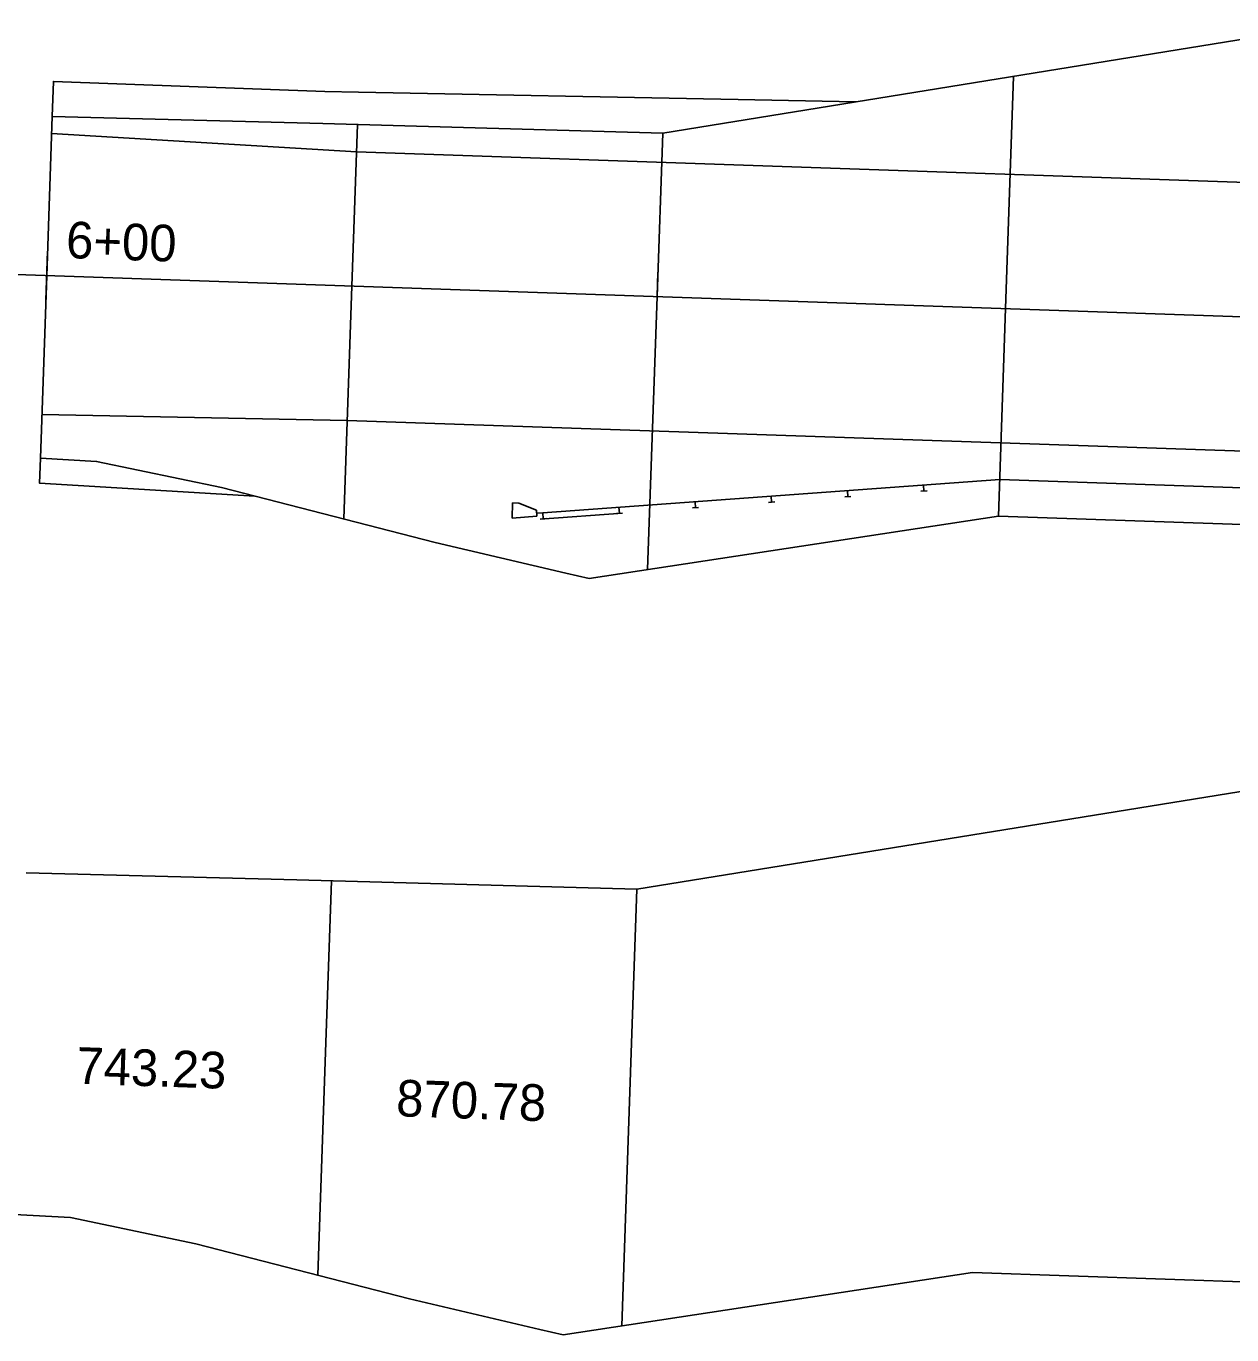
# Model space of a CAD drawing. Extents: x 2191309 to 2193046, y 863659 to 865133.
# Drawn here: x 2191516.5 to 2191615.2, y 865006.3 to 865113.4 of the extents above; entities that cross this region are included whole.
import ezdxf

# ---------------------------------------------------------------- set-up
doc = ezdxf.new("R2010")
doc.units = 0
for name, color, linetype in [('D_Guardrail_Beam_Rt', 7, 'Continuous'), ('D_Guardrail_End_MidSplice', 7, 'Continuous'), ('D_Roadway_Centerline', 7, 'Continuous'), ('D_Roadway_Centerline_Text', 7, 'Continuous'), ('D_Roadway_Drive_Gravel', 7, 'Continuous'), ('D_Roadway_Edge_Shoulder', 7, 'Continuous'), ('D_Roadway_Edge_TW', 7, 'Continuous'), ('FRAME', 7, 'Continuous'), ('JUNK', 7, 'Continuous')]:
    doc.layers.add(name, color=color, linetype=linetype)

msp = doc.modelspace()

# ---------------------------------------------------------------- linework, layer by layer
at = {"layer": 'D_Guardrail_Beam_Rt'}
msp.add_line((2191596.21, 865076.32), (2191668.04, 865073.86), dxfattribs=at)
at = {"layer": 'D_Guardrail_End_MidSplice'}
for p, q in [((2191596.21, 865076.32), (2191558.81, 865073.61)), ((2191589.97, 865075.87), (2191590.01, 865075.37)), ((2191571.27, 865074.51), (2191571.31, 865074.01)), ((2191577.51, 865074.97), (2191577.54, 865074.47)), ((2191584.03, 865074.94), (2191583.53, 865074.9)), ((2191583.74, 865075.42), (2191583.78, 865074.92)), ((2191590.26, 865075.39), (2191589.76, 865075.36)), ((2191556.29, 865073.17), (2191556.33, 865074.42)), ((2191556.33, 865074.42), (2191556.83, 865074.4)), ((2191556.83, 865074.4), (2191558.29, 865073.82)), ((2191558.29, 865073.82), (2191558.33, 865073.32)), ((2191558.81, 865073.61), (2191558.31, 865073.57)), ((2191565.32, 865073.58), (2191558.59, 865073.09)), ((2191558.81, 865073.61), (2191558.84, 865073.11)), ((2191565.32, 865073.58), (2191564.83, 865073.54)), ((2191565.04, 865074.06), (2191565.08, 865073.56)), ((2191571.56, 865074.03), (2191571.06, 865074)), ((2191577.79, 865074.49), (2191577.29, 865074.45)), ((2191558.33, 865073.32), (2191556.29, 865073.17)), ((2191559.09, 865073.13), (2191558.59, 865073.09))]:
    msp.add_line(p, q, dxfattribs=at)
at = {"layer": 'D_Roadway_Centerline'}
msp.add_line((2191489.64, 865093.99), (2191792.64, 865083.59), dxfattribs=at)
at = {"layer": 'D_Roadway_Centerline_Text'}
for points in [[(2191518.26, 865095.01), (2191518.12, 865091.01)], [(2191568.23, 865093.29), (2191568.16, 865091.3)]]:
    msp.add_lwpolyline(points, dxfattribs=at)
at = {"layer": 'D_Roadway_Drive_Gravel'}
for points in [[(2191518.64, 865106.05), (2191518.64, 865106.05), (2191518.74, 865108.92), (2191540.96, 865108.08), (2191543.72, 865108.03), (2191574.81, 865107.43), (2191584.44, 865107.24)], [(2191517.68, 865078.07), (2191517.61, 865076.02), (2191535.24, 865074.96)]]:
    msp.add_lwpolyline(points, dxfattribs=at)
at = {"layer": 'D_Roadway_Edge_Shoulder'}
for p, q in [((2191622.71, 865113.44), (2191568.62, 865104.69)), ((2191518.19, 865093.01), (2191518.64, 865106.05)), ((2191517.68, 865078.07), (2191518.19, 865093.01)), ((2191562.6, 865068.22), (2191596.1, 865073.33)), ((2191596.1, 865073.33), (2191697, 865069.86)), ((2191620.58, 865051.53), (2191566.49, 865042.78)), ((2191560.48, 865006.31), (2191593.98, 865011.42)), ((2191593.98, 865011.42), (2191694.88, 865007.95))]:
    msp.add_line(p, q, dxfattribs=at)
for points in [[(2191568.62, 865104.69), (2191540.8, 865105.46), (2191518.64, 865106.05)], [(2191517.68, 865078.07), (2191522.27, 865077.81), (2191532.51, 865075.66), (2191550, 865071.18), (2191560.68, 865068.67), (2191562.6, 865068.22)], [(2191566.49, 865042.78), (2191538.67, 865043.55), (2191516.51, 865044.14)], [(2191515.55, 865016.16), (2191520.14, 865015.91), (2191530.39, 865013.75), (2191547.88, 865009.27), (2191558.56, 865006.76), (2191560.48, 865006.31)]]:
    msp.add_lwpolyline(points, dxfattribs=at)
at = {"layer": 'D_Roadway_Edge_TW'}
for points in [[(2191518.59, 865104.66), (2191543.55, 865103.15), (2191648.1, 865099.56), (2191698.08, 865101.18)], [(2191517.8, 865081.65), (2191542.8, 865081.16), (2191647.35, 865077.57), (2191697.09, 865072.53)]]:
    msp.add_lwpolyline(points, dxfattribs=at)
at = {"layer": 'JUNK'}
for p, q in [((2191596.69, 865090.32), (2191597.34, 865109.33)), ((2191543.17, 865092.15), (2191543.63, 865105.38)), ((2191568.16, 865091.3), (2191568.62, 865104.69)), ((2191542.52, 865073.1), (2191543.17, 865092.15)), ((2191567.39, 865068.95), (2191568.16, 865091.3)), ((2191596.1, 865073.33), (2191596.69, 865090.32)), ((2191541.05, 865030.24), (2191541.5, 865043.47)), ((2191566.03, 865029.39), (2191566.49, 865042.78)), ((2191540.4, 865011.19), (2191541.05, 865030.24)), ((2191565.27, 865007.04), (2191566.03, 865029.39))]:
    msp.add_line(p, q, dxfattribs=at)

# ---------------------------------------------------------------- texts
at = {"layer": 'D_Roadway_Centerline_Text'}
msp.add_text('6+00', height=3, rotation=358.0343, dxfattribs=at).set_placement((2191519.74, 865094.46))
at = {"layer": 'FRAME'}
for s, p in [('743.23', (2191520.59, 865026.87)), ('870.78', (2191546.77, 865024.21))]:
    msp.add_text(s, height=3, rotation=358.0343, dxfattribs=at).set_placement(p)

doc.saveas('drawing.dxf')
